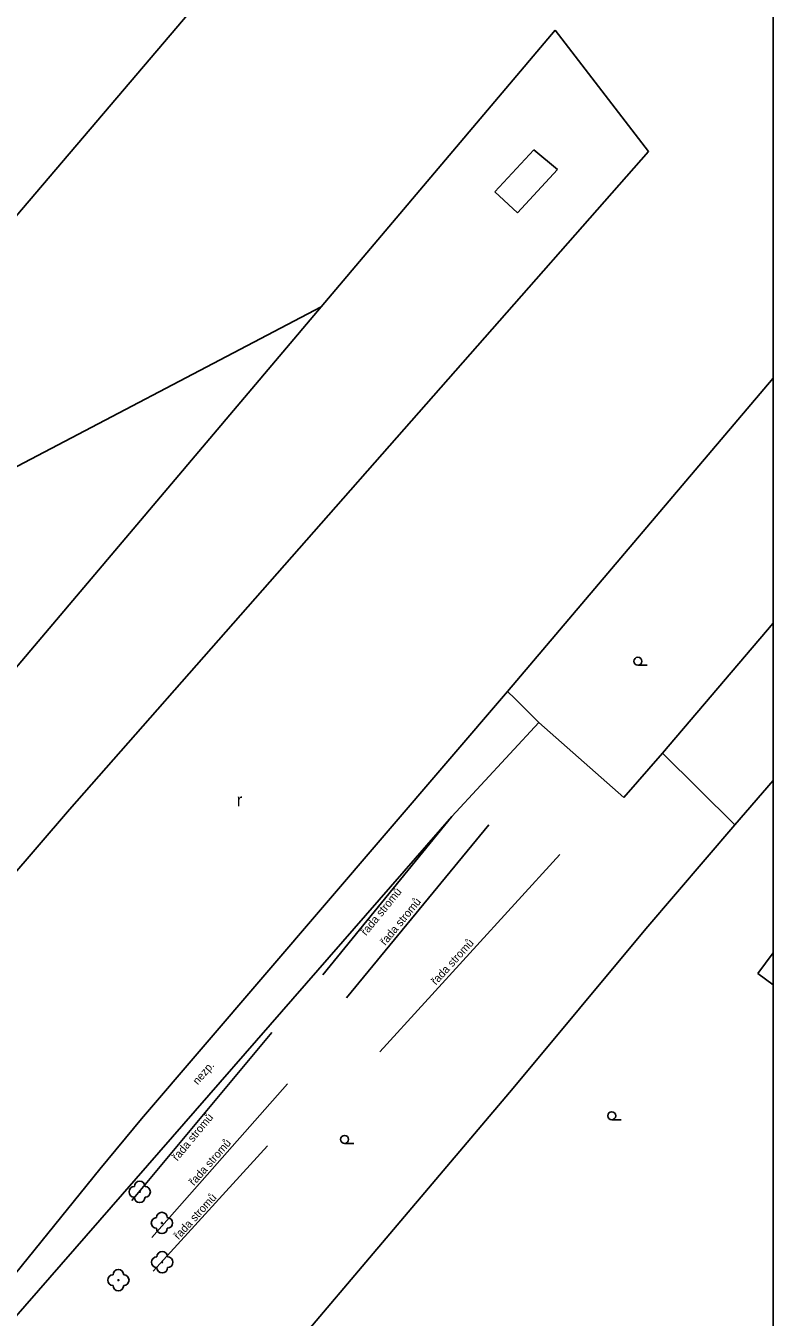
# Model space of a CAD drawing. Extents: x -594386 to -594050, y -1167541 to -1167175.
# Drawn here: x -594119.8 to -594049.8, y -1167451.4 to -1167330.4 of the extents above; entities that cross this region are included whole.
import ezdxf

# ---------------------------------------------------------------- set-up
doc = ezdxf.new("R2010")
doc.units = 0
for name, color, linetype in [('Level 22', 7, 'Continuous'), ('Level 36', 7, 'Continuous'), ('Level 41', 7, 'Continuous'), ('Vrstva 11', 7, 'Continuous'), ('Vrstva 40', 7, 'Continuous'), ('Vrstva 51', 7, 'Continuous'), ('Vrstva 52', 7, 'Continuous'), ('Vrstva 63', 7, 'Continuous'), ('Vrstva 7', 7, 'Continuous'), ('Vrstva 8', 7, 'Continuous')]:
    doc.layers.add(name, color=color, linetype=linetype)

msp = doc.modelspace()

# ---------------------------------------------------------------- linework, layer by layer
at = {"layer": 'Level 22'}
for centre in [(-594109.15, -1167439.66), (-594107.07, -1167442.57), (-594107.04, -1167446.25), (-594111.15, -1167447.93)]:
    msp.add_circle(centre, 0.05, dxfattribs=at)
for centre, start, end in [((-594109.15, -1167439.16), 0, 180), ((-594109.65, -1167439.66), 90, 270), ((-594109.15, -1167440.16), 180, 0), ((-594108.65, -1167439.66), 270, 90), ((-594107.57, -1167442.57), 90, 270), ((-594107.07, -1167442.07), 0, 180), ((-594106.57, -1167442.57), 270, 90), ((-594107.07, -1167443.07), 180, 0), ((-594107.54, -1167446.25), 90, 270), ((-594107.04, -1167445.75), 0, 180), ((-594106.54, -1167446.25), 270, 90), ((-594111.65, -1167447.93), 90, 270), ((-594111.15, -1167447.43), 0, 180), ((-594110.65, -1167447.93), 270, 90), ((-594107.04, -1167446.75), 180, 0), ((-594111.15, -1167448.43), 180, 0)]:
    msp.add_arc(centre, 0.5, start, end, dxfattribs=at)
at = {"layer": 'Level 36'}
for p, q in [((-594062.44, -1167390.32), (-594061.57, -1167390.32)), ((-594064.89, -1167432.91), (-594064.02, -1167432.91)), ((-594089.94, -1167435.11), (-594089.07, -1167435.11))]:
    msp.add_line(p, q, dxfattribs=at)
for centre in [(-594062.44, -1167389.94), (-594064.89, -1167432.53), (-594089.94, -1167434.74)]:
    msp.add_circle(centre, 0.375, dxfattribs=at)
at = {"layer": 'Vrstva 11'}
for points in [[(-594061.45, -1167342.17), (-594070.19, -1167330.81)], [(-594124.45, -1167373.66), (-594092.14, -1167356.73)], [(-594121, -1167451.58), (-594079.89, -1167404.5), (-594071.72, -1167395.67)], [(-594115.73, -1167403.84), (-594139.08, -1167430.97)]]:
    msp.add_lwpolyline(points, dxfattribs=at)
at = {"layer": 'Vrstva 51'}
for p, q in [((-594049.75, -1167363.42), (-594074.66, -1167392.76)), ((-594060.12, -1167398.55), (-594049.75, -1167386.38)), ((-594049.75, -1167401.12), (-594053.34, -1167405.27))]:
    msp.add_line(p, q, dxfattribs=at)
for points in [[(-594068.61, -1167287), (-594162.26, -1167396.94)], [(-594070.19, -1167330.81), (-594092.14, -1167356.73)], [(-594061.45, -1167342.17), (-594115.73, -1167403.84)], [(-594075.84, -1167345.97), (-594072.18, -1167342.02)], [(-594072.18, -1167342.02), (-594069.99, -1167343.87)], [(-594069.99, -1167343.87), (-594073.73, -1167347.92)], [(-594073.73, -1167347.92), (-594075.84, -1167345.97)], [(-594092.14, -1167356.73), (-594147.11, -1167421.67)]]:
    msp.add_lwpolyline(points, dxfattribs=at)
at = {"layer": 'Vrstva 52'}
for p, q in [((-594051.19, -1167419.2), (-594049.75, -1167417.27)), ((-594049.75, -1167420.27), (-594051.19, -1167419.2))]:
    msp.add_line(p, q, dxfattribs=at)
at = {"layer": 'Vrstva 63'}
msp.add_lwpolyline([(-594386.36, -1167175.43), (-594049.75, -1167175.43), (-594049.75, -1167540.79), (-594386.36, -1167540.79)], close=True, dxfattribs=at)
at = {"layer": 'Vrstva 7'}
for points in [[(-594112.89, -1167437.53), (-594108.97, -1167432.82), (-594074.66, -1167392.76)], [(-594073.98, -1167393.42), (-594074.66, -1167392.76)], [(-594071.72, -1167395.67), (-594063.74, -1167402.69)], [(-594063.74, -1167402.69), (-594060.12, -1167398.55)], [(-594053.34, -1167405.27), (-594060.12, -1167398.55)], [(-594091.97, -1167419.33), (-594079.89, -1167404.5)], [(-594107.12, -1167468.87), (-594074.13, -1167429.94), (-594061.69, -1167415.02), (-594053.34, -1167405.27)], [(-594076.41, -1167405.28), (-594089.77, -1167421.49)], [(-594069.76, -1167408.03), (-594086.62, -1167426.54)], [(-594109.88, -1167440.48), (-594096.77, -1167424.71)], [(-594095.3, -1167429.53), (-594108.01, -1167443.94)], [(-594097.16, -1167435.35), (-594107.88, -1167447.1)], [(-594112.89, -1167437.53), (-594122.67, -1167449.58)]]:
    msp.add_lwpolyline(points, dxfattribs=at)
at = {"layer": 'Vrstva 8'}
msp.add_lwpolyline([(-594071.72, -1167395.67), (-594073.98, -1167393.42)], dxfattribs=at)

# ---------------------------------------------------------------- texts
at = {"layer": 'Level 36'}
msp.add_text('r', height=1.2, dxfattribs=at).set_placement((-594100.06, -1167403.54))
at = {"layer": 'Level 41'}
for rotation, p in [(50.8349, (-594087.92, -1167415.7)), (50.5052, (-594086.12, -1167416.62)), (47.6709, (-594081.37, -1167420.33)), (50.2624, (-594105.62, -1167436.81)), (48.5869, (-594104.06, -1167439.13)), (47.6026, (-594105.5, -1167444.18))]:
    msp.add_text('řada stromů', height=0.75, rotation=rotation, dxfattribs=at).set_placement(p)
at = {"layer": 'Vrstva 40'}
msp.add_text('nezp.', height=0.75, rotation=49.0581, dxfattribs=at).set_placement((-594103.71, -1167429.68))

doc.saveas('drawing.dxf')
